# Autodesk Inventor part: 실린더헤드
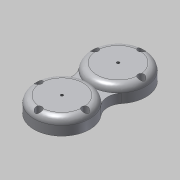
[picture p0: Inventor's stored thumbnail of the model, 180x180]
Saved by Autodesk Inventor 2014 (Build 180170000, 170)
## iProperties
Created: 2016-11
Part Number: 실린더헤드
Material: 알루미늄 6061
Document SubType Name: Modeling
Designer: mduedu
Density: 2.71 g/cm^3
Mass: 538.465 g
Surface Area: 423.673 cm^2
Volume: 198.695 cm^3
Appearance: 알루미늄 - 평지
Author: mduedu
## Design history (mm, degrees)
sketch "스케치1"
  geometry: C1 r 42 at (0, 0); 1 further point
  constraints: 1 centre point, 1 coincident
  dimensions: "d0" = 84 diameter of C1
extrude "돌출1" new body sketch "스케치1" distance "d1" = 24; taper "d2" = 0 deg
fillet "모깎기1" dims "d3" = 10
sketch "스케치2"
  geometry: C1 r 30 at (0, 0); 1 further point
  constraints: 1 centre point, 1 coincident
  dimensions: "d4" = 60 diameter of C1
extrude "돌출2" join sketch "스케치2" distance "d5" = 5; taper "d6" = 0 deg
sketch "스케치3"
  geometry: C1 r 25 at (0, 0); 1 further point
  constraints: 1 centre point, 1 coincident
  dimensions: "d7" = 50 diameter of C1
extrude "돌출3" cut sketch "스케치3" distance "d8" = 20; taper "d9" = 0 deg
hole "구멍1" diameter "d12" = 4.134; stored, may be unused: countersink angle "d16" = 90 deg, drill point angle "d18" = 118 deg; dims "d10" = 10, "d11" = 10, "d13" = 6, "d14" = 4, "d15" = 2, "d17" = 8
chamfer "모따기1" distance "d19" = 1; stored, may be unused: second distance "d20" = 2, angle "d21" = 45 deg
fillet "모깎기2" dims "d22" = 3
sketch "스케치4"
  geometry: C1 r 17.5 at (0, 0); 1 further point
  constraints: 1 centre point, 1 coincident
  dimensions: "d23" = 35 diameter of C1
extrude "돌출4" cut sketch "스케치4" distance "d24" = 2; taper "d25" = 0 deg
fillet "모깎기3" dims "d26" = 0.5
sketch "스케치5" dims "d32" = 70
  geometry: C1 r 5 at (0, 35); 3 further points
  constraints: 2 coincident, 2 vertical alignment, 1 centre point, 2 other
  dimensions: "d33" = 10 diameter of C1
extrude "돌출5" cut sketch "스케치5" distance "d34" = 10; taper "d35" = 0 deg
sketch "스케치6"
  geometry: A1 r 35 centre (0, -35) between (0, 0) and (-35, -35); 2 further points
  constraints: 3 point on circle, 2 horizontal alignment, 1 centre point, 1 coincident, 1 vertical alignment
  dimensions: "d39" = 70 diameter of A1
hole "구멍3" sketch "스케치6" at (0, 0), (-35, -35), (35, -35) diameter "d57" = 5.5; stored, may be unused: countersink angle "d61" = 90 deg, drill point angle "d63" = 118 deg; dims "d58" = 6, "d59" = 4, "d60" = 2, "d62" = 8
chamfer "모따기2" distance "d54" = 5; stored, may be unused: second distance "d55" = 2, angle "d56" = 30 deg
node "작업 평면1"
sketch "스케치8"
  geometry: L1 (0, 85)-(0, 0); A1 r 42 centre (0, 85) between (-32.469, 58.358) and (32.469, 58.358) reference; A2 r 42 centre (0, 0) between (-32.469, 26.642) and (32.469, 26.642) reference; A3 r 25 centre (51.795, 42.5) between (32.469, 26.642) and (32.469, 58.358); A4 r 25 centre (-51.795, 42.5) between (-32.469, 58.358) and (-32.469, 26.642); A5 r 25 centre (-51.795, 42.5) between (-32.469, 26.642) and (-32.469, 58.358); A6 r 25 centre (51.795, 42.5) between (32.469, 58.358) and (32.469, 26.642); A7 r 42 centre (0, 85) between (-32.469, 58.358) and (32.469, 58.358); A8 r 42 centre (0, 0) between (32.469, 26.642) and (-32.469, 26.642); 1 further point
  constraints: 16 point on circle, 6 centre point, 2 coincident, 2 end point, 2 tangent, 1 symmetric about line, 1 vertical, 1 other
  dimensions: "d65" = 50 diameter of A3
extrude "돌출6" join sketch "스케치8" distance "d67" = 14; taper "d68" = 0 deg
node "솔리드1"
pattern_circular "원형 패턴1" dims angle "d37" = 360 deg
mirror "대칭1"
other parameters: "d64" = 42.5
